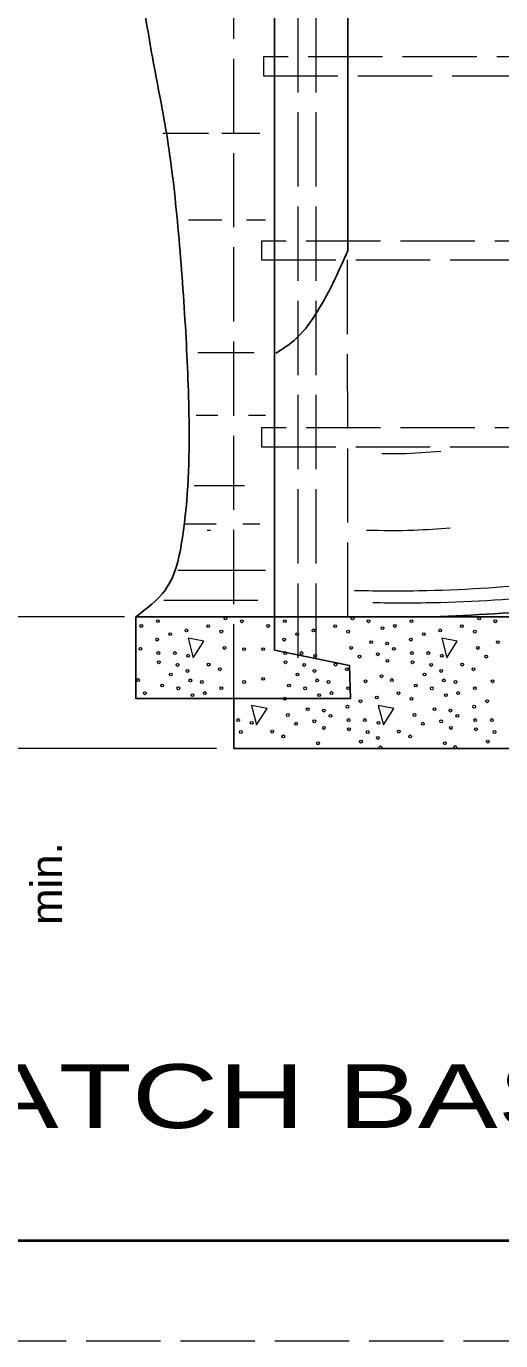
# Model space of a CAD drawing. Extents: x 1329.9 to 1363.9, y 715.5 to 737.5.
# Drawn here: x 1339.48 to 1341.85, y 715.5 to 722.08 of the extents above; entities that cross this region are included whole.
import ezdxf
from ezdxf.enums import TextEntityAlignment as Align

# ---------------------------------------------------------------- set-up
doc = ezdxf.new("R2010")
doc.units = 0
doc.header["$LTSCALE"] = 0.062
doc.linetypes.add('LONG_DASHED', pattern=[7.5, 6, -1.5])
doc.layers.add('1', color=7, linetype='Continuous', lineweight=13)

msp = doc.modelspace()

# ---------------------------------------------------------------- linework, layer by layer
at = {"layer": '1', "linetype": 'LONG_DASHED'}
for p, q in [((1340.83683, 718.91875), (1340.83683, 728.63117)), ((1340.92608, 718.91875), (1340.92608, 728.63467)), ((1340.5145, 718.71467), (1340.5145, 723.72467)), ((1341.08508, 719.1235), (1341.08317, 720.95475))]:
    msp.add_line(p, q, dxfattribs=at)
at = {"layer": '1', "lineweight": 25}
for p, q in [((1341.08508, 720.95883), (1341.08508, 723.53967)), ((1340.71817, 718.95617), (1340.71817, 723.33767)), ((1341.09825, 718.71467), (1340.47867, 718.71467))]:
    msp.add_line(p, q, dxfattribs=at)
at = {"layer": '1'}
for p, q in [((1340.15875, 721.54658), (1340.38733, 721.54658)), ((1340.454, 721.54658), (1340.64458, 721.54658)), ((1340.28725, 721.11283), (1340.454, 721.11283)), ((1340.57792, 721.11283), (1340.67325, 721.11283)), ((1340.33483, 720.44708), (1340.61608, 720.44708)), ((1340.32533, 720.13433), (1340.43508, 720.13433)), ((1340.5875, 720.13433), (1340.67325, 720.13433)), ((1340.31592, 719.78133), (1340.56842, 719.78133)), ((1340.26817, 719.58967), (1340.4255, 719.58967)), ((1340.55883, 719.58967), (1340.64458, 719.58967)), ((1340.38117, 719.55725), (1340.39692, 719.55725)), ((1340.23492, 719.35758), (1340.67325, 719.35758)), ((1340.16333, 719.20633), (1340.63508, 719.20633)), ((1339.96792, 719.1235), (1338.58108, 719.1235)), ((1340.02358, 719.1235), (1340.5145, 719.1235)), ((1340.42842, 718.46475), (1338.60475, 718.46475))]:
    msp.add_line(p, q, dxfattribs=at)
at = {"layer": '1', "linetype": 'LONG_DASHED'}
for points in [[(1329.86333, 715.4975), (1363.86333, 715.4975), (1363.86333, 737.4975), (1329.86333, 737.4975)], [(1345.97833, 721.92783), (1340.6625, 721.92783), (1340.6625, 721.83283), (1345.97833, 721.83283)], [(1345.96808, 721.00608), (1340.65225, 721.00608), (1340.65225, 720.91108), (1345.96808, 720.91108)], [(1345.96875, 720.07075), (1340.65292, 720.07075), (1340.65292, 719.97583), (1345.96875, 719.97583)]]:
    msp.add_lwpolyline(points, close=True, dxfattribs=at)
at = {"layer": '1', "lineweight": 25}
for points in [[(1363.36333, 715.9975), (1331.86333, 715.9975), (1331.86333, 736.9975)], [(1346.13117, 728.65933), (1346.13117, 718.46475), (1340.5145, 718.46475), (1340.5145, 718.71467)], [(1340.02358, 719.1235), (1340.5145, 719.1235), (1346.13117, 719.1235)], [(1340.47867, 718.71467), (1340.02358, 718.71467), (1340.02358, 719.1235)], [(1340.71817, 718.95617), (1341.09317, 718.87908), (1341.09825, 718.71467)]]:
    msp.add_lwpolyline(points, dxfattribs=at)
at = {"layer": '1', "lineweight": 40}
msp.add_lwpolyline([(1331.86333, 736.9975), (1363.36333, 736.9975), (1363.36333, 715.9975), (1331.86333, 715.9975)], close=True, dxfattribs=at)
msp.add_lwpolyline([(1331.86333, 736.9975), (1363.36333, 736.9975), (1363.36333, 715.9975), (1331.86333, 715.9975)], close=True, dxfattribs=at)
at = {"layer": '1'}
for points in [[(1340.2855, 719.01608), (1340.31117, 718.91867), (1340.36342, 719.00083)], [(1341.55433, 719.01608), (1341.58, 718.91867), (1341.63217, 719.00083)], [(1340.60275, 718.68017), (1340.62842, 718.58292), (1340.68067, 718.66508)], [(1341.23717, 718.68017), (1341.26275, 718.58292), (1341.315, 718.66508)]]:
    msp.add_lwpolyline(points, close=True, dxfattribs=at)
for centre in [(1340.47317, 719.11545), (1341.10757, 719.11545), (1341.74197, 719.11545), (1340.05145, 719.07767), (1340.13456, 719.10208), (1340.27788, 719.05557), (1340.38663, 719.07644), (1340.45176, 719.04924), (1340.55395, 719.10124), (1340.68585, 719.07767), (1340.76896, 719.10208), (1340.91228, 719.05557), (1341.02103, 719.07644), (1341.08616, 719.04924), (1341.18835, 719.10124), (1341.25856, 719.06676), (1341.32025, 719.07767), (1341.40336, 719.10208), (1341.54668, 719.05557), (1341.65542, 719.07644), (1341.72056, 719.04924), (1341.82275, 719.10124), (1340.13144, 719.00933), (1340.19647, 719.03654), (1340.76584, 719.00933), (1340.83087, 719.03654), (1341.20093, 718.99668), (1341.28176, 718.98969), (1341.40024, 719.00933), (1341.46526, 719.03654), (1341.83533, 718.99668), (1340.04664, 718.9631), (1340.13657, 718.94223), (1340.21883, 718.94223), (1340.28645, 718.92862), (1340.4672, 718.96764), (1340.56594, 718.96151), (1340.66126, 718.96151), (1340.77097, 718.94223), (1340.85323, 718.94223), (1340.92084, 718.92862), (1341.10159, 718.96764), (1341.14273, 718.92409), (1341.23434, 718.9359), (1341.31544, 718.9631), (1341.40537, 718.94223), (1341.48763, 718.94223), (1341.55524, 718.92862), (1341.73599, 718.96764), (1341.77712, 718.92409), (1340.13911, 718.89599), (1340.23252, 718.88239), (1340.28301, 718.85245), (1340.38837, 718.88418), (1340.44489, 718.86062), (1340.7735, 718.89599), (1340.86692, 718.88239), (1340.91741, 718.85245), (1341.02277, 718.88418), (1341.07929, 718.86062), (1341.28261, 718.90293), (1341.4079, 718.89599), (1341.50132, 718.88239), (1341.55181, 718.85245), (1341.65717, 718.88418), (1341.71368, 718.86062), (1340.03607, 718.80683), (1340.19906, 718.83431), (1340.29675, 718.80532), (1340.35411, 718.79709), (1340.56594, 718.79709), (1340.66126, 718.813), (1340.83346, 718.83431), (1340.93115, 718.80532), (1340.98851, 718.79709), (1341.17381, 718.80051), (1341.25263, 718.82586), (1341.30487, 718.80683), (1341.46785, 718.83431), (1341.56555, 718.80532), (1341.62291, 718.79709), (1341.80821, 718.80051), (1340.06943, 718.74062), (1340.15597, 718.77963), (1340.23675, 718.76541), (1340.30696, 718.73094), (1340.36865, 718.74185), (1340.45176, 718.76625), (1340.79037, 718.77963), (1340.87115, 718.76541), (1340.94136, 718.73094), (1341.00305, 718.74185), (1341.08616, 718.76625), (1341.22948, 718.71974), (1341.33823, 718.74062), (1341.42477, 718.77963), (1341.50555, 718.76541), (1341.57576, 718.73094), (1341.63745, 718.74185), (1341.72056, 718.76625), (1340.76896, 718.71342), (1340.88373, 718.66086), (1340.96456, 718.65387), (1341.08304, 718.67351), (1341.14806, 718.70071), (1341.40336, 718.71342), (1341.51813, 718.66086), (1341.59896, 718.65387), (1341.71744, 718.67351), (1341.78246, 718.70071), (1340.53603, 718.6064), (1340.60364, 718.5928), (1340.7844, 718.63181), (1340.82553, 718.58827), (1340.91714, 718.60008), (1340.99824, 718.62728), (1341.08817, 718.6064), (1341.17043, 718.6064), (1341.23804, 718.5928), (1341.41879, 718.63181), (1341.45992, 718.58827), (1341.55154, 718.60008), (1341.63264, 718.62728), (1341.72257, 718.6064), (1341.80483, 718.6064), (1340.54972, 718.54657), (1340.70557, 718.54836), (1340.76209, 718.5248), (1340.96541, 718.56711), (1341.0907, 718.56017), (1341.18412, 718.54657), (1341.33997, 718.54836), (1341.39648, 718.5248), (1341.59981, 718.56711), (1341.7251, 718.56017), (1341.81852, 718.54657), (1340.93544, 718.49004), (1341.15066, 718.49849), (1341.23461, 718.51663), (1341.24835, 718.4695), (1341.56983, 718.49004), (1341.62207, 718.47101), (1341.78505, 718.49849)]:
    msp.add_ellipse(centre, major_axis=(0, 0.00718), ratio=0.944544, dxfattribs=at)
at = {"layer": '1', "lineweight": 25}
for points in [[(1340.02358, 719.1235), (1340.172, 719.25925), (1340.257, 719.52042), (1340.29025, 720.1055), (1340.27175, 720.58058), (1340.23458, 721.07567), (1340.17708, 721.54742), (1340.10675, 721.92825), (1340.04675, 722.26367), (1339.99383, 722.49733)], [(1341.53892, 719.12392), (1341.54858, 719.12442), (1342.16333, 719.16225), (1342.55242, 719.20425), (1342.97442, 719.27833), (1343.37542, 719.36125), (1343.934, 719.52492), (1344.35258, 719.725), (1344.76942, 719.9795), (1344.9655, 720.14458), (1345.15825, 720.32783), (1345.30867, 720.529), (1345.44808, 720.78467), (1345.49958, 720.93375), (1345.54217, 721.19308)], [(1340.724, 720.44383), (1340.81392, 720.5065), (1340.92158, 720.63567), (1341.00933, 720.79375), (1341.08508, 720.95883)]]:
    msp.add_spline(points, degree=3, dxfattribs=at)
at = {"layer": '1'}
for points in [[(1341.2545, 719.94142), (1341.34842, 719.9415), (1341.55042, 719.95392)], [(1341.17825, 719.55792), (1341.41525, 719.55817), (1341.5975, 719.56942)], [(1341.11867, 719.25525), (1341.48192, 719.25558), (1342.09658, 719.29342), (1342.48567, 719.33542), (1342.90775, 719.4095), (1343.30867, 719.49242), (1343.32567, 719.49742)], [(1341.20933, 719.19483), (1341.5105, 719.19508), (1342.12517, 719.23292), (1342.48833, 719.27217)]]:
    msp.add_spline(points, degree=3, dxfattribs=at)

# ---------------------------------------------------------------- texts
at = {"layer": '1', "width": 1.05}
msp.add_text('min.', height=0.156, rotation=90, dxfattribs=at).set_placement((1339.65392, 717.78708), align=Align.CENTER)
at = {"layer": '1', "width": 1.4}
msp.add_text('CATCH BASINS No. 2-5 & No. 2-6', height=0.32, dxfattribs=at).set_placement((1343.43337, 716.56258), align=Align.CENTER)

doc.saveas('drawing.dxf')
